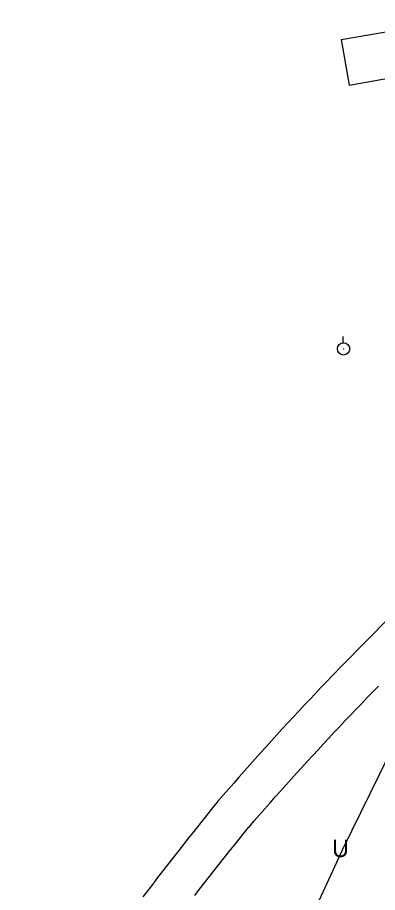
# Model space of a CAD drawing. Extents: x 1282810 to 1284464, y 402460 to 405899.
# Drawn here: x 1283501.3 to 1283626, y 404466.8 to 404770.2 of the extents above; entities that cross this region are included whole.
import ezdxf

# ---------------------------------------------------------------- set-up
doc = ezdxf.new("R2010")
doc.units = 0
for name, color, linetype in [('Default', 7, 'Continuous'), ('MOT_Driveway_Stage 2', 7, 'Continuous'), ('MOT_Proposed Road_Stage 2', 7, 'Continuous'), ('MOT_Shld_Stage 2', 7, 'Continuous'), ('MOT_Stage 1_Conc Ditch Paving', 7, 'Continuous'), ('S_UNDERGROUND_CABLE', 7, 'Continuous'), ('S_UTILITY_POLE', 7, 'Continuous'), ('S_UTL_PT_SYM', 7, 'Continuous')]:
    doc.layers.add(name, color=color, linetype=linetype)

msp = doc.modelspace()

# ---------------------------------------------------------------- linework, layer by layer
at = {"layer": 'MOT_Driveway_Stage 2'}
for p, q in [((1283613.47, 404762.48), (1283657.44, 404770.15)), ((1283613.47, 404762.48), (1283616.22, 404746.72)), ((1283616.22, 404746.72), (1283660.19, 404754.39))]:
    msp.add_line(p, q, dxfattribs=at)
at = {"layer": 'MOT_Proposed Road_Stage 2'}
msp.add_arc((1284344.24, 403884.33), 905.47, 138.45801, 157.33333, dxfattribs=at)
at = {"layer": 'MOT_Shld_Stage 2'}
msp.add_arc((1284344.24, 403884.33), 913.47, 136.3373, 157.33333, dxfattribs=at)
at = {"layer": 'MOT_Stage 1_Conc Ditch Paving'}
for points in [[(1283630.35, 404562.28), (1283613.68, 404545.41), (1283610.3, 404541.9), (1283608.37, 404539.89), (1283606.44, 404537.86), (1283604.52, 404535.83), (1283602.6, 404533.8), (1283600.68, 404531.76), (1283598.77, 404529.72), (1283596.87, 404527.67), (1283594.97, 404525.61), (1283593.07, 404523.55), (1283591.18, 404521.49), (1283589.3, 404519.42), (1283587.42, 404517.34), (1283585.54, 404515.26), (1283583.68, 404513.18), (1283581.81, 404511.09), (1283579.95, 404508.99), (1283578.1, 404506.89), (1283576.25, 404504.79), (1283574.41, 404502.68), (1283572.57, 404500.56), (1283570.74, 404498.45), (1283570.53, 404498.21), (1283568.91, 404496.21), (1283567.15, 404494.03), (1283565.4, 404491.85), (1283563.65, 404489.66), (1283561.9, 404487.47), (1283560.16, 404485.27), (1283558.43, 404483.07), (1283556.7, 404480.87), (1283554.98, 404478.66), (1283553.27, 404476.44), (1283551.56, 404474.22), (1283549.85, 404472), (1283548.15, 404469.77), (1283546.46, 404467.54), (1283544.77, 404465.3)], [(1283562.73, 404465.79), (1283564.42, 404467.98), (1283566.11, 404470.16), (1283567.81, 404472.34), (1283569.51, 404474.52), (1283571.22, 404476.69), (1283572.94, 404478.86), (1283574.66, 404481.02), (1283576.38, 404483.18), (1283578.12, 404485.33), (1283579.85, 404487.48), (1283581.4, 404489.38), (1283581.54, 404489.55), (1283583.35, 404491.64), (1283585.17, 404493.73), (1283586.99, 404495.81), (1283588.81, 404497.88), (1283590.64, 404499.96), (1283592.47, 404502.02), (1283594.31, 404504.08), (1283596.16, 404506.14), (1283598.01, 404508.19), (1283599.86, 404510.23), (1283601.72, 404512.28), (1283603.59, 404514.31), (1283605.46, 404516.34), (1283607.33, 404518.37), (1283609.21, 404520.39), (1283611.09, 404522.41), (1283612.98, 404524.42), (1283614.88, 404526.42), (1283616.78, 404528.42), (1283618.68, 404530.42), (1283620.59, 404532.41), (1283622.5, 404534.39), (1283624.42, 404536.37), (1283626.35, 404538.35)]]:
    msp.add_lwpolyline(points, dxfattribs=at)
at = {"layer": 'S_UNDERGROUND_CABLE'}
for p, q in [((1283613.96, 404481.66), (1283649.71, 404554.77)), ((1283586.9, 404423.34), (1283613.96, 404481.66))]:
    msp.add_line(p, q, dxfattribs=at)
at = {"layer": 'S_UTILITY_POLE'}
msp.add_line((1283614.17, 404657.41), (1283614.17, 404659.52), dxfattribs=at)
msp.add_circle((1283614.29, 404655.27), 2.13, dxfattribs=at)
at = {"layer": 'S_UTL_PT_SYM'}
msp.add_lwpolyline([(1283614.31, 404655.29), (1283614.31, 404655.33), (1283614.31, 404655.29), (1283614.26, 404655.29), (1283614.31, 404655.29), (1283614.31, 404655.23), (1283614.31, 404655.29), (1283614.36, 404655.29)], dxfattribs=at)
msp.add_lwpolyline([(1283614.31, 404655.29), (1283614.31, 404655.33), (1283614.31, 404655.29), (1283614.26, 404655.29), (1283614.31, 404655.29), (1283614.31, 404655.23), (1283614.31, 404655.29), (1283614.36, 404655.29)], dxfattribs=at)

# ---------------------------------------------------------------- texts
at = {"layer": 'Default'}
msp.add_text('U', height=6, rotation=360, dxfattribs=at).set_placement((1283610.33, 404479.12))

doc.saveas('drawing.dxf')
